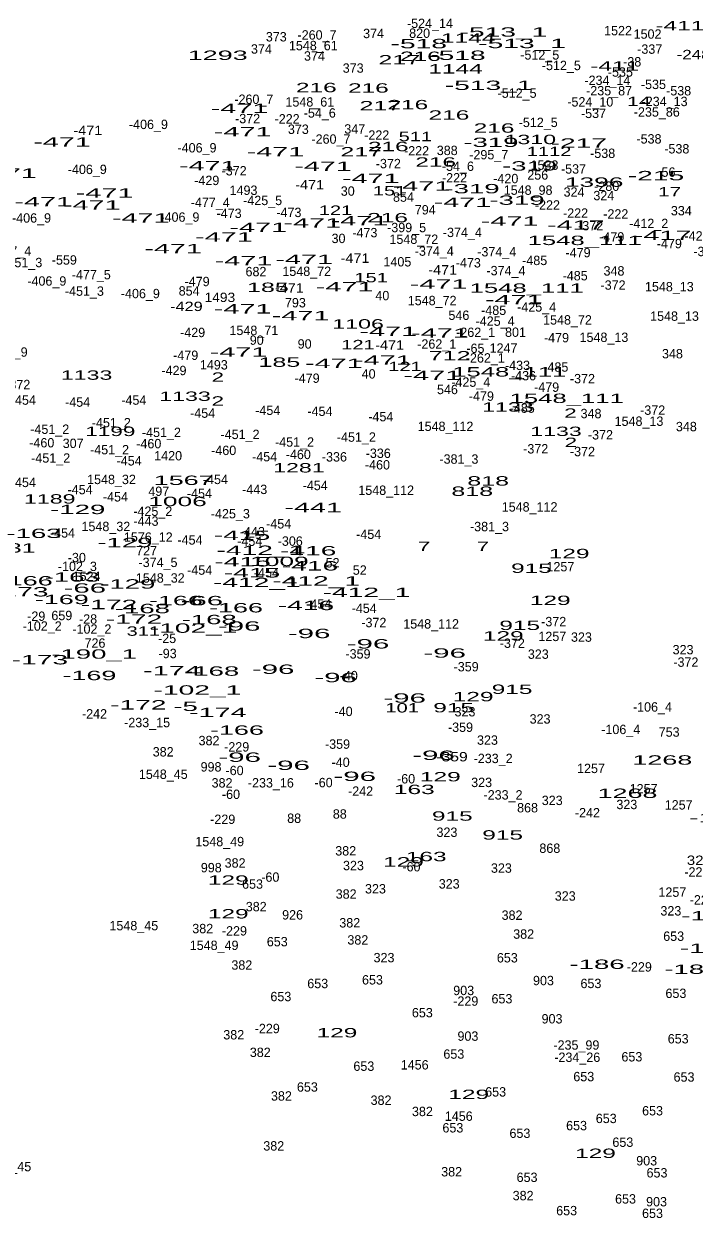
# Model space of a CAD drawing. Extents: x -660434 to -656144, y -997850 to -994016.
# Drawn here: x -659014 to -658728, y -996078 to -995569 of the extents above; entities that cross this region are included whole.
import ezdxf
from ezdxf.enums import TextEntityAlignment as Align

# ---------------------------------------------------------------- set-up
doc = ezdxf.new("R2010")
doc.units = 0
doc.header["$LTSCALE"] = 1.6
doc.layers.add('24', color=7, linetype='Continuous')

msp = doc.modelspace()

# ---------------------------------------------------------------- texts
at = {"layer": '24'}
for s, p in [('-524_14', (-658840.814, -995570.43)), ('373', (-658906.443, -995576.16)), ('-260_7', (-658889.047, -995575.38)), ('374', (-658864.897, -995574.75)), ('820', (-658845.221, -995574.64)), ('1522', (-658760.49, -995573.54)), ('1502', (-658747.894, -995575)), ('374', (-658912.797, -995581.37)), ('1548_61', (-658890.631, -995579.92)), ('-337', (-658746.961, -995581.43)), ('374', (-658890.147, -995584.35)), ('-512_5', (-658793.916, -995583.9)), ('-512_5', (-658784.706, -995588.41)), ('-38', (-658754.435, -995586.86)), ('373', (-658873.603, -995589.52)), ('-535', (-658759.495, -995591.22)), ('-234_14', (-658765.044, -995594.75)), ('-535', (-658745.375, -995596.48)), ('-260_7', (-658916.017, -995602.83)), ('-512_5', (-658803.616, -995600.22)), ('-235_87', (-658764.317, -995599.19)), ('-234_13', (-658740.619, -995603.77)), ('-538', (-658734.615, -995599.2)), ('1548_61', (-658892.121, -995603.97)), ('-54_6', (-658887.872, -995608.68)), ('-524_10', (-658772.343, -995603.95)), ('-537', (-658770.971, -995608.86)), ('-235_86', (-658743.947, -995608.26)), ('-406_9', (-658961.042, -995613.56)), ('-372', (-658918.691, -995611.09)), ('-222', (-658901.815, -995611.2)), ('-512_5', (-658794.586, -995612.71)), ('373', (-658897.023, -995615.64)), ('347', (-658872.927, -995615.51)), ('-222', (-658863.535, -995618.11)), ('-406_9', (-658940.302, -995623.55)), ('-260_7', (-658883.097, -995619.83)), ('-538', (-658747.285, -995619.75)), ('-538', (-658735.385, -995623.98)), ('-222', (-658846.545, -995624.84)), ('388', (-658833.437, -995624.67)), ('-295_7', (-658815.704, -995626.5)), ('-538', (-658767.065, -995625.9)), ('-406_9', (-658987.152, -995632.77)), ('-372', (-658924.451, -995633.36)), ('-372', (-658858.591, -995630.3)), ('-54_6', (-658828.872, -995631.43)), ('1533', (-658791.9, -995630.95)), ('-537', (-658779.511, -995632.59)), ('56', (-658738.953, -995633.94)), ('-429', (-658936.125, -995637.48)), ('-222', (-658830.325, -995636.36)), ('-420', (-658808.423, -995636.69)), ('256', (-658794.783, -995635.15)), ('1493', (-658920.44, -995641.68)), ('30', (-658875.921, -995642.03)), ('854', (-658852.131, -995644.6)), ('1548_98', (-658798.897, -995641.63)), ('324', (-658779.291, -995642.42)), ('324', (-658766.571, -995643.96)), ('-280', (-658765.329, -995639.96)), ('-477_4', (-658934.652, -995646.88)), ('-425_5', (-658912.267, -995646.03)), ('-222', (-658790.635, -995647.97)), ('-406_9', (-659010.962, -995653.51)), ('-406_9', (-658947.602, -995653.13)), ('-473', (-658926.595, -995651.52)), ('-473', (-658901.055, -995651.14)), ('794', (-658842.823, -995650.02)), ('-222', (-658778.635, -995651.43)), ('-222', (-658761.445, -995651.79)), ('334', (-658733.471, -995650.41)), ('-473', (-658868.605, -995659.78)), ('-399_5', (-658850.783, -995657.6)), ('-374_4', (-658826.976, -995659.67)), ('-372', (-658772.191, -995656.81)), ('-412_2', (-658747.39, -995655.86)), ('30', (-658879.861, -995662.24)), ('1548_72', (-658847.697, -995662.59)), ('-479', (-658763.16, -995661.59)), ('-479', (-658738.58, -995664.47)), ('-427', (-658726.755, -995661.18)), ('-467_4', (-659019.422, -995667.65)), ('-374_4', (-658838.976, -995667.65)), ('-374_4', (-658812.286, -995667.93)), ('-479', (-658777.56, -995668.31)), ('-307', (-658722.994, -995667.82)), ('-451_3', (-659014.7, -995672.54)), ('-559', (-658996.96, -995671.44)), ('1405', (-658854.718, -995672.21)), ('-473', (-658824.445, -995672.65)), ('-485', (-658796.089, -995671.63)), ('-477_5', (-658985.448, -995677.72)), ('682', (-658915.113, -995676.41)), ('1548_72', (-658893.437, -995676.28)), ('-374_4', (-658808.356, -995675.99)), ('-485', (-658778.809, -995678.16)), ('348', (-658762.221, -995676.11)), ('-406_9', (-659004.432, -995680.41)), ('-451_3', (-658988.39, -995684.74)), ('854', (-658943.661, -995684.65)), ('-479', (-658940.25, -995680.64)), ('-372', (-658762.621, -995682.15)), ('1548_13', (-658738.586, -995682.84)), ('-406_9', (-658964.492, -995685.78)), ('793', (-658898.288, -995689.69)), ('40', (-658861.145, -995686.65)), ('1548_72', (-658839.877, -995688.76)), ('546', (-658828.457, -995695.04)), ('-485', (-658813.609, -995692.91)), ('-425_4', (-658795.251, -995691.5)), ('1548_13', (-658736.376, -995695.42)), ('-425_4', (-658813.011, -995697.55)), ('1548_72', (-658782.077, -995697.02)), ('-429', (-658942.175, -995702.39)), ('1548_71', (-658916.021, -995701.5)), ('90', (-658914.777, -995705.66)), ('-262_1', (-658821.302, -995702.32)), ('801', (-658804.29, -995702.27)), ('-479', (-658786.78, -995704.62)), ('1548_13', (-658766.516, -995704.45)), ('-406_9', (-659020.952, -995710.75)), ('90', (-658894.327, -995707.29)), ('-262_1', (-658837.912, -995707.31)), ('-65', (-658821.4, -995709.15)), ('1247', (-658809.39, -995709.04)), ('-479', (-658945.11, -995712.12)), ('-262_1', (-658817.182, -995713.26)), ('348', (-658737.261, -995711.45)), ('-429', (-658950.145, -995718.62)), ('1493', (-658933.11, -995716.2)), ('40', (-658867.005, -995720.07)), ('-433', (-658803.429, -995716.44)), ('-436', (-658800.865, -995720.84)), ('-485', (-658787.059, -995717.15)), ('-372', (-659016.841, -995724.62)), ('-479', (-658893.27, -995721.92)), ('-425_4', (-658823.381, -995723.58)), ('-479', (-658791, -995725.74)), ('-372', (-658775.681, -995722.1)), ('546', (-658833.357, -995726.73)), ('-479', (-658818.84, -995729.57)), ('-454', (-659014.463, -995731.25)), ('-454', (-658991.283, -995732.11)), ('-454', (-658967.273, -995731.25)), ('-454', (-658910.083, -995735.63)), ('-454', (-658887.803, -995736.02)), ('-485', (-658801.419, -995734.68)), ('-372', (-658745.721, -995735.55)), ('-451_2', (-658976.9, -995740.9)), ('-454', (-658937.903, -995736.82)), ('-454', (-658861.793, -995738.32)), ('348', (-658772.021, -995737)), ('1548_13', (-658751.546, -995740.27)), ('-451_2', (-659003.18, -995743.69)), ('-451_2', (-658955.49, -995745.03)), ('-451_2', (-658921.93, -995745.9)), ('1548_112', (-658834.17, -995742.46)), ('-372', (-658768.001, -995746.08)), ('348', (-658731.311, -995742.57)), ('-460', (-659006.579, -995749.46)), ('307', (-658993.187, -995749.72)), ('-460', (-658960.879, -995749.85)), ('-451_2', (-658898.65, -995749.16)), ('-451_2', (-658872.25, -995747.05)), ('-451_2', (-659002.79, -995755.98)), ('-451_2', (-658977.64, -995752.43)), ('1420', (-658952.628, -995755.02)), ('-460', (-658928.909, -995752.73)), ('-454', (-658911.423, -995755.42)), ('-460', (-658897.039, -995754.46)), ('-336', (-658881.62, -995755.49)), ('-336', (-658862.9, -995753.96)), ('-381_3', (-658828.446, -995756.43)), ('-372', (-658795.651, -995752.06)), ('-372', (-658775.681, -995753.22)), ('-454', (-658969.293, -995757.18)), ('-460', (-658863.239, -995758.88)), ('-454', (-659014.463, -995766.4)), ('1548_32', (-658976.822, -995765.13)), ('-454', (-658932.443, -995765.12)), ('-454', (-658990.223, -995769.47)), ('497', (-658956.613, -995770.18)), ('-454', (-658939.263, -995771.09)), ('-443', (-658915.663, -995769.37)), ('-454', (-658889.823, -995767.71)), ('1548_112', (-658859.51, -995769.74)), ('-454', (-658975.123, -995772.55)), ('1548_112', (-658798.26, -995776.85)), ('-425_2', (-658959.177, -995778.71)), ('-425_3', (-658926.057, -995779.76)), ('1548_32', (-658979.212, -995785.2)), ('-443', (-658962.093, -995782.92)), ('-454', (-658905.423, -995784.08)), ('-381_3', (-658815.386, -995785.24)), ('-454', (-658997.733, -995787.97)), ('1576_12', (-658961.103, -995789.74)), ('-454', (-658943.293, -995790.95)), ('-454', (-658917.763, -995791.5)), ('-443', (-658916.623, -995787.43)), ('-306', (-658900.474, -995791.46)), ('-454', (-658866.973, -995788.54)), ('727', (-658961.819, -995795.55)), ('-102_3', (-658991.39, -995802.24)), ('-30', (-658991.619, -995798.49)), ('-374_5', (-658956.952, -995800.54)), ('52', (-658882.407, -995800.71)), ('1257', (-658785.106, -995802.37)), ('1524', (-658987.474, -995806.44)), ('1548_32', (-658955.982, -995807.19)), ('-454', (-658939.163, -995803.82)), ('-454', (-658910.653, -995804.94)), ('52', (-658870.787, -995803.83)), ('-454', (-658888.283, -995818.29)), ('-454', (-658868.893, -995820.11)), ('-102_2', (-659006.41, -995827.71)), ('-29', (-659008.95, -995823.51)), ('659', (-658998.038, -995823.21)), ('-28', (-658986.815, -995824.71)), ('-372', (-658864.771, -995826.21)), ('1548_112', (-658840.31, -995826.79)), ('-372', (-658787.971, -995825.82)), ('-102_2', (-658985.19, -995828.99)), ('-25', (-658953.055, -995832.98)), ('1257', (-658788.566, -995832.14)), ('323', (-658776.127, -995832.43)), ('726', (-658983.868, -995834.98)), ('-372', (-658805.631, -995835.04)), ('323', (-658732.727, -995837.8)), ('-93', (-658952.84, -995839.44)), ('-359', (-658871.55, -995839.61)), ('323', (-658794.557, -995839.71)), ('-372', (-658731.521, -995843.11)), ('-359', (-658825.37, -995845.08)), ('-40', (-658875.493, -995848.88)), ('-106_4', (-658745.8, -995862.25)), ('-242', (-658984.059, -995865.2)), ('-233_15', (-658961.605, -995868.9)), ('-40', (-658877.703, -995864.15)), ('323', (-658825.857, -995864.3)), ('323', (-658793.787, -995867.37)), ('-359', (-658827.77, -995870.92)), ('-106_4', (-658759.34, -995871.85)), ('753', (-658738.673, -995872.97)), ('382', (-658935.167, -995876.61)), ('-359', (-658880.29, -995878.12)), ('323', (-658816.257, -995876.4)), ('382', (-658954.747, -995881.41)), ('-229', (-658923.35, -995879.29)), ('998', (-658934.308, -995887.83)), ('-40', (-658878.953, -995885.86)), ('-233_2', (-658813.832, -995884.23)), ('1257', (-658772.046, -995888.49)), ('1548_45', (-658954.697, -995890.98)), ('-60', (-658924.254, -995889.36)), ('-60', (-658851.014, -995892.91)), ('382', (-658929.597, -995894.66)), ('-233_16', (-658908.761, -995894.64)), ('-60', (-658886.234, -995894.54)), ('-242', (-658870.449, -995898.18)), ('323', (-658818.747, -995894.46)), ('1257', (-658749.586, -995897.16)), ('-60', (-658925.784, -995899.54)), ('-233_2', (-658809.602, -995899.79)), ('323', (-658788.607, -995902.14)), ('323', (-658756.737, -995903.88)), ('1257', (-658734.606, -995904.05)), ('88', (-658879.317, -995907.94)), ('868', (-658799.133, -995905.27)), ('-242', (-658773.559, -995907.4)), ('-229', (-658929.31, -995910.21)), ('88', (-658898.807, -995909.76)), ('1548_49', (-658930.592, -995919.72)), ('323', (-658833.557, -995915.74)), ('382', (-658876.797, -995923.67)), ('868', (-658789.623, -995922.56)), ('382', (-658924.027, -995928.85)), ('323', (-658873.477, -995929.95)), ('998', (-658934.208, -995930.85)), ('-60', (-658908.984, -995934.88)), ('-60', (-658848.714, -995930.46)), ('323', (-658810.317, -995931.04)), ('-229', (-658726.83, -995932.69)), ('653', (-658916.583, -995937.86)), ('323', (-658864.087, -995939.88)), ('323', (-658832.597, -995937.77)), ('382', (-658876.607, -995942.11)), ('323', (-658783.057, -995942.95)), ('1257', (-658737.296, -995941.31)), ('-229', (-658724.53, -995944.6)), ('382', (-658915.007, -995947.49)), ('323', (-658737.937, -995949.29)), ('926', (-658899.478, -995951)), ('382', (-658875.067, -995954.4)), ('382', (-658805.757, -995951.14)), ('1548_45', (-658967.277, -995955.62)), ('382', (-658937.857, -995956.86)), ('-229', (-658924.31, -995957.85)), ('382', (-658800.797, -995959.2)), ('653', (-658736.733, -995960.11)), ('1548_49', (-658932.992, -995964.02)), ('653', (-658906.023, -995962.45)), ('382', (-658871.607, -995961.7)), ('323', (-658860.437, -995969.27)), ('653', (-658807.773, -995969.33)), ('382', (-658921.147, -995972.42)), ('-229', (-658751.41, -995973.22)), ('653', (-658888.743, -995980.31)), ('653', (-658865.373, -995978.74)), ('903', (-658792.337, -995979.05)), ('653', (-658772.063, -995980.28)), ('653', (-658904.483, -995985.88)), ('903', (-658826.417, -995983.28)), ('653', (-658735.773, -995984.5)), ('-229', (-658825.52, -995987.81)), ('653', (-658810.073, -995986.81)), ('653', (-658844.063, -995992.76)), ('903', (-658788.687, -995995.38)), ('-229', (-658910.3, -995999.53)), ('382', (-658924.607, -996002.19)), ('903', (-658824.597, -996002.77)), ('653', (-658734.813, -996003.9)), ('382', (-658913.277, -996009.69)), ('653', (-658830.623, -996010.43)), ('-235_99', (-658778.282, -996006.57)), ('653', (-658754.583, -996011.59)), ('653', (-658869.043, -996015.6)), ('1456', (-658847.34, -996015.03)), ('-234_26', (-658777.901, -996011.8)), ('653', (-658775.133, -996020.04)), ('653', (-658732.313, -996020.23)), ('653', (-658893.163, -996024.49)), ('653', (-658812.763, -996026.57)), ('382', (-658904.257, -996028.31)), ('382', (-658861.697, -996030.13)), ('382', (-658844.037, -996034.93)), ('1456', (-658828.52, -996036.94)), ('653', (-658745.753, -996034.63)), ('653', (-658831.023, -996041.91)), ('653', (-658778.203, -996040.97)), ('653', (-658765.533, -996037.9)), ('653', (-658802.393, -996044.24)), ('382', (-658907.517, -996049.63)), ('653', (-658758.443, -996048.06)), ('903', (-658748.267, -996055.98)), ('1548_45', (-659021.497, -996058.46)), ('382', (-658831.557, -996060.67)), ('653', (-658743.853, -996061.12)), ('653', (-658799.343, -996063.04)), ('382', (-658801.027, -996070.85)), ('653', (-658757.293, -996072.26)), ('653', (-658782.443, -996077.26)), ('903', (-658744.047, -996073.46)), ('653', (-658745.773, -996078.41))]:
    msp.add_text(s, height=4, dxfattribs=at).set_placement(p, align=Align.CENTER)
for s, width, p in [('-411', 1.95, (-658734.082, -995571.44)), ('1144', 1.95, (-658824.515, -995576.73)), ('-513_1', 2.25, (-658809.427, -995574.12)), ('-518', 2.25, (-658845.591, -995579.07)), ('-513_1', 2.25, (-658801.457, -995579.02)), ('1293', 2.15, (-658931.443, -995584.05)), ('217', 2, (-658853.903, -995585.98)), ('216', 1.95, (-658844.893, -995584.49)), ('-518', 2.25, (-658829.081, -995584.06)), ('-248_2', 1.35, (-658724.21, -995583.75)), ('1144', 1.95, (-658829.895, -995589.85)), ('-411', 1.95, (-658761.902, -995588.63)), ('216', 1.95, (-658889.343, -995597.83)), ('216', 1.95, (-658867.103, -995598.02)), ('-513_1', 2.25, (-658815.757, -995596.88)), ('-471', 2.3, (-658922.131, -995606.73)), ('217', 2, (-658861.973, -995605.58)), ('216', 1.95, (-658850.273, -995605.13)), ('14', 1.7, (-658751.603, -995603.78)), ('216', 1.95, (-658832.703, -995609.55)), ('-471', 1.15, (-658986.91, -995616.14)), ('-471', 2.3, (-658920.791, -995616.72)), ('511', 1.6, (-658847.044, -995618.73)), ('216', 1.95, (-658813.433, -995615.12)), ('-471', 2.3, (-658997.921, -995621.06)), ('216', 1.95, (-658858.623, -995623)), ('-319', 2.2, (-658814.785, -995621.22)), ('1310', 1.85, (-658797.96, -995620)), ('-217', 2.25, (-658777.235, -995621.54)), ('-471', 2.3, (-658906.811, -995625.27)), ('217', 2, (-658870.133, -995625.26)), ('1112', 1.6, (-658789.95, -995625.11)), ('-471', 2.3, (-658935.711, -995631.24)), ('-471', 2.3, (-658886.461, -995631.41)), ('216', 1.95, (-658838.363, -995629.62)), ('-319', 2.2, (-658798.265, -995631.3)), ('-471', 2.3, (-659021.021, -995634.39)), ('-471', 1.15, (-658892.201, -995639.36)), ('-471', 2.3, (-658866.101, -995636.6)), ('1396', 2.1, (-658770.687, -995638.21)), ('-215', 2.25, (-658744.281, -995635.44)), ('-471', 2.3, (-658979.731, -995642.84)), ('151', 1.6, (-658858.054, -995641.91)), ('-471', 2.3, (-658844.411, -995639.85)), ('-319', 2.2, (-658822.845, -995641)), ('17', 1.65, (-658738.493, -995642.34)), ('-471', 2.3, (-659005.981, -995646.6)), ('-471', 2.3, (-658985.241, -995647.95)), ('-471', 2.3, (-658826.931, -995646.78)), ('-319', 2.2, (-658803.645, -995645.9)), ('-471', 2.3, (-658964.321, -995653.52)), ('121', 1.6, (-658881.134, -995650.19)), ('-471', 2.3, (-658870.901, -995654.65)), ('216', 1.95, (-658858.913, -995653.38)), ('-471', 2.3, (-658914.111, -995657.54)), ('-471', 2.3, (-658891.061, -995655.61)), ('-471', 2.3, (-658806.771, -995654.84)), ('-417', 2.3, (-658778.541, -995656.55)), ('-471', 2.3, (-658928.791, -995661.59)), ('1548_111', 2.05, (-658774.733, -995663.08)), ('-417', 2.3, (-658741.481, -995660.97)), ('-471', 2.3, (-658950.491, -995666.58)), ('-471', 2.3, (-658920.441, -995671.75)), ('-471', 2.3, (-658894.521, -995671.16)), ('-471', 1.15, (-658872.801, -995670.67)), ('151', 1.6, (-658865.934, -995678.98)), ('-471', 1.15, (-658835.361, -995675.66)), ('185', 2, (-658910.017, -995683.11)), ('-471', 1.15, (-658900.841, -995683.35)), ('-471', 2.3, (-658877.241, -995682.89)), ('-471', 2.3, (-658837.111, -995681.74)), ('1548_111', 2.05, (-658799.503, -995683.45)), ('1493', 1.1, (-658930.54, -995687.4)), ('-471', 2.3, (-658805.041, -995688.35)), ('-429', 1.3, (-658944.821, -995691.25)), ('-471', 2.3, (-658920.831, -995692.3)), ('-471', 2.3, (-658896.061, -995695.18)), ('1106', 1.85, (-658871.505, -995698.73)), ('-471', 2.3, (-658858.611, -995701.91)), ('-471', 2.3, (-658836.531, -995702.67)), ('-471', 2.3, (-658922.551, -995710.74)), ('121', 1.6, (-658871.554, -995707.58)), ('-471', 1.15, (-658858.02, -995707.74)), ('185', 2, (-658905.127, -995715.07)), ('-471', 2.3, (-658881.851, -995715.54)), ('-471', 2.3, (-658860.921, -995714.2)), ('712', 2, (-658832.423, -995712.35)), ('1133', 1.85, (-658987.454, -995720.58)), ('121', 1.6, (-658851.484, -995716.9)), ('-471', 2.3, (-658839.801, -995720.73)), ('1548_111', 2.05, (-658806.943, -995719.2)), ('2', 1.8, (-658931.431, -995721.45)), ('1133', 1.85, (-658945.404, -995729.61)), ('1548_111', 2.05, (-658782.413, -995730.5)), ('2', 1.8, (-658931.431, -995731.63)), ('1133', 1.85, (-658807.534, -995734.22)), ('2', 1.8, (-658780.831, -995736.81)), ('1199', 1.8, (-658977.323, -995744.62)), ('1133', 1.85, (-658786.994, -995744.59)), ('2', 1.8, (-658780.641, -995749.3)), ('1281', 1.85, (-658896.784, -995760.15)), ('1567', 2.15, (-658945.977, -995765.49)), ('818', 2, (-658815.947, -995765.75)), ('818', 2, (-658822.757, -995770.16)), ('1189', 1.85, (-659003.179, -995773.44)), ('1006', 2.1, (-658948.615, -995774.52)), ('-129', 2.2, (-658991.225, -995777.93)), ('-441', 2.3, (-658890.712, -995777.12)), ('-163', 2.2, (-659009.915, -995788.14)), ('-129', 2.2, (-658971.095, -995792.07)), ('-415', 2.25, (-658921.046, -995788.95)), ('-31', 2, (-659016.931, -995794.37)), ('-412_1', 2.25, (-658913.223, -995795.37)), ('-416', 2.25, (-658892.821, -995795.58)), ('7', 1.8, (-658843.306, -995793.64)), ('7', 1.8, (-658818.156, -995793.64)), ('129', 1.95, (-658781.373, -995796.76)), ('-415', 2.25, (-658920.856, -995800.28)), ('1009', 2.1, (-658905.095, -995800.11)), ('-416', 2.25, (-658892.051, -995802.01)), ('-163', 2.2, (-658993.595, -995806.78)), ('-415', 2.25, (-658916.826, -995804.99)), ('915', 1.95, (-658797.483, -995803.02)), ('-166', 2.15, (-659013.429, -995808.39)), ('-66', 2.35, (-658988.203, -995811.48)), ('-129', 2.2, (-658969.845, -995809.74)), ('-412_1', 2.25, (-658914.753, -995809.11)), ('-412_1', 2.25, (-658889.413, -995808.43)), ('-173', 2.25, (-659015.755, -995813.08)), ('-169', 2.15, (-658998.039, -995816.36)), ('-166', 2.15, (-658949.299, -995816.84)), ('-66', 2.35, (-658938.223, -995816.86)), ('-412_1', 2.25, (-658867.903, -995813.33)), ('129', 1.95, (-658789.443, -995816.74)), ('-172', 2.25, (-658977.855, -995818.52)), ('-168', 2.2, (-658963.605, -995820.23)), ('-166', 2.15, (-658923.629, -995819.9)), ('-416', 2.25, (-658893.781, -995818.92)), ('-172', 2.25, (-658967.195, -995824.77)), ('-168', 2.2, (-658935.095, -995824.94)), ('-96', 2.35, (-658922.273, -995827.71)), ('915', 1.95, (-658802.483, -995827.42)), ('311', 1.6, (-658963.234, -995829.87)), ('-102_1', 2.25, (-658941.744, -995828.6)), ('-96', 2.35, (-658892.413, -995830.88)), ('129', 1.95, (-658809.503, -995831.91)), ('-96', 2.35, (-658867.263, -995835.3)), ('-173', 2.25, (-659007.395, -995842.09)), ('-190_1', 2.2, (-658984.199, -995839.66)), ('-96', 2.35, (-658834.523, -995839.23)), ('-174', 2.3, (-658951.011, -995846.75)), ('-168', 2.2, (-658934.035, -995846.93)), ('-96', 2.35, (-658907.783, -995846.15)), ('-169', 2.15, (-658986.229, -995848.82)), ('-96', 2.35, (-658881.093, -995849.7)), ('-102_1', 2.25, (-658940.114, -995855.01)), ('-96', 2.35, (-658851.613, -995858.44)), ('129', 1.95, (-658822.373, -995857.84)), ('915', 1.95, (-658805.743, -995854.69)), ('-172', 2.25, (-658965.375, -995861.35)), ('-5', 2.2, (-658945.194, -995862)), ('101', 1.6, (-658852.7, -995862.62)), ('915', 1.95, (-658830.703, -995862.57)), ('-174', 2.3, (-658931.421, -995864.61)), ('-166', 2.15, (-658923.239, -995872.14)), ('-96', 2.35, (-658922.083, -995883.7)), ('-96', 2.35, (-658839.283, -995882.88)), ('-359', 1.25, (-658831.38, -995883.5)), ('-96', 2.35, (-658901.153, -995887.16)), ('1268', 2.15, (-658741.573, -995884.89)), ('-96', 2.35, (-658872.933, -995891.86)), ('129', 1.95, (-658836.383, -995892.03)), ('163', 1.95, (-658847.493, -995897.45)), ('1268', 2.15, (-658756.463, -995899.1)), ('915', 1.95, (-658831.283, -995908.82)), ('-133', 2.25, (-658718.061, -995909.53)), ('915', 1.95, (-658809.773, -995916.89)), ('129', 1.95, (-658852.133, -995928.38)), ('163', 1.95, (-658842.403, -995926.11)), ('323', 1.2, (-658725.76, -995927.7)), ('129', 1.95, (-658926.953, -995936.16)), ('129', 1.95, (-658926.953, -995950.55)), ('-133', 2.25, (-658721.521, -995951.41)), ('-133', 2.25, (-658722.091, -995965.24)), ('-186', 2.2, (-658769.445, -995972.09)), ('-186', 2.2, (-658728.955, -995974.22)), ('129', 1.95, (-658880.533, -996001.32)), ('129', 1.95, (-658824.273, -996027.63)), ('129', 1.95, (-658770.123, -996052.79))]:
    msp.add_text(s, height=4, dxfattribs=dict(at, width=width)).set_placement(p, align=Align.CENTER)

doc.saveas('drawing.dxf')
